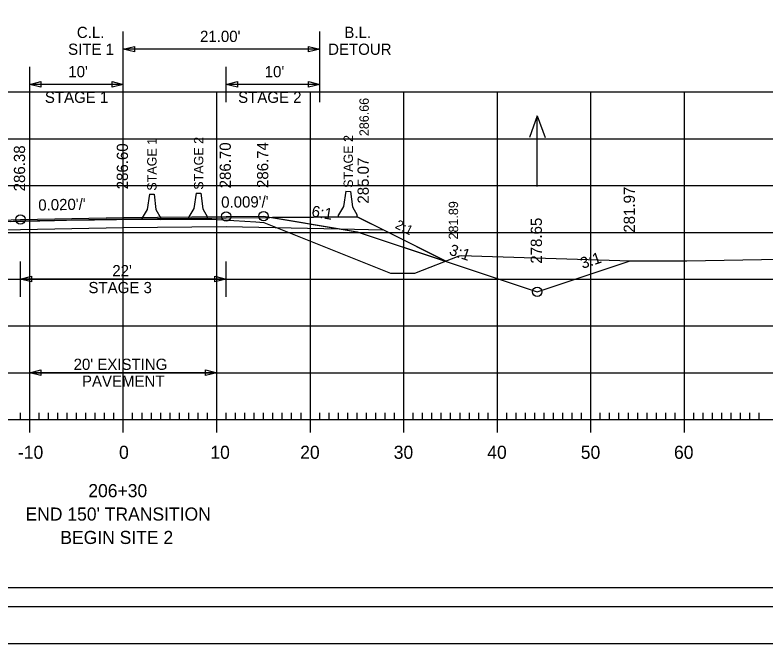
# Model space of a CAD drawing. Extents: x 1368713 to 1370673, y 380279 to 380950.
# Drawn here: x 1370498.1 to 1370578.3, y 380523.8 to 380591 of the extents above; entities that cross this region are included whole.
import ezdxf

# ---------------------------------------------------------------- set-up
doc = ezdxf.new("R2010")
doc.units = 0
for name, color, linetype in [('R_Alt Surface', 7, 'Continuous'), ('R_Axis', 7, 'Continuous'), ('R_Axis Annot', 7, 'Continuous'), ('R_Border', 7, 'Continuous'), ('R_CONC BARRIER', 7, 'Continuous'), ('R_Exist Surface', 7, 'Continuous'), ('R_Fin Surface', 7, 'Continuous'), ('R_Grid', 7, 'Continuous'), ('R_No Plot', 7, 'Continuous'), ('R_ROW Annot', 7, 'Continuous'), ('R_Stage 3 EW', 7, 'Continuous'), ('R_Water Annot', 7, 'Continuous'), ('R_Xsect Elev', 7, 'Continuous'), ('R_Xsect Slope', 7, 'Continuous')]:
    doc.layers.add(name, color=color, linetype=linetype)

msp = doc.modelspace()

# ---------------------------------------------------------------- linework, layer by layer
at = {"layer": 'R_Alt Surface'}
msp.add_line((1370532.811, 380568.128), (1370537.39, 380568.036), dxfattribs=at)
for points in [[(1370477.259, 380564.764), (1370477.379, 380564.724), (1370484.629, 380567.14), (1370487.788, 380567.667), (1370494.629, 380568.807), (1370498.629, 380568.967), (1370509.629, 380569.187), (1370520.629, 380569.288), (1370534.629, 380569.416), (1370537.737, 380567.862), (1370544.179, 380564.641)], [(1370524.629, 380569.491), (1370534.629, 380567.825)], [(1370487.788, 380567.834), (1370498.629, 380568.05), (1370509.629, 380568.27), (1370520.629, 380568.371), (1370532.811, 380568.128)], [(1370534.629, 380567.825), (1370553.886, 380561.406)], [(1370553.886, 380561.406), (1370553.886, 380561.406), (1370563.829, 380564.72)]]:
    msp.add_lwpolyline(points, dxfattribs=at)
at = {"layer": 'R_Axis'}
for p, q in [((1370499.629, 380546.354), (1370499.629, 380549.154)), ((1370509.629, 380546.354), (1370509.629, 380549.154)), ((1370519.629, 380546.354), (1370519.629, 380549.154)), ((1370529.629, 380546.354), (1370529.629, 380549.154)), ((1370539.629, 380546.354), (1370539.629, 380549.154)), ((1370549.629, 380546.354), (1370549.629, 380549.154)), ((1370559.629, 380546.354), (1370559.629, 380549.154)), ((1370569.629, 380546.354), (1370569.629, 380549.154)), ((1370498.629, 380547.754), (1370498.629, 380548.454)), ((1370500.629, 380547.754), (1370500.629, 380548.454)), ((1370501.629, 380547.754), (1370501.629, 380548.454)), ((1370502.629, 380547.754), (1370502.629, 380548.454)), ((1370503.629, 380547.754), (1370503.629, 380548.454)), ((1370504.629, 380547.754), (1370504.629, 380548.454)), ((1370505.629, 380547.754), (1370505.629, 380548.454)), ((1370506.629, 380547.754), (1370506.629, 380548.454)), ((1370507.629, 380547.754), (1370507.629, 380548.454)), ((1370508.629, 380547.754), (1370508.629, 380548.454)), ((1370510.629, 380547.754), (1370510.629, 380548.454)), ((1370511.629, 380547.754), (1370511.629, 380548.454)), ((1370512.629, 380547.754), (1370512.629, 380548.454)), ((1370513.629, 380547.754), (1370513.629, 380548.454)), ((1370514.629, 380547.754), (1370514.629, 380548.454)), ((1370515.629, 380547.754), (1370515.629, 380548.454)), ((1370516.629, 380547.754), (1370516.629, 380548.454)), ((1370517.629, 380547.754), (1370517.629, 380548.454)), ((1370518.629, 380547.754), (1370518.629, 380548.454)), ((1370520.629, 380547.754), (1370520.629, 380548.454)), ((1370521.629, 380547.754), (1370521.629, 380548.454)), ((1370522.629, 380547.754), (1370522.629, 380548.454)), ((1370523.629, 380547.754), (1370523.629, 380548.454)), ((1370524.629, 380547.754), (1370524.629, 380548.454)), ((1370525.629, 380547.754), (1370525.629, 380548.454)), ((1370526.629, 380547.754), (1370526.629, 380548.454)), ((1370527.629, 380547.754), (1370527.629, 380548.454)), ((1370528.629, 380547.754), (1370528.629, 380548.454)), ((1370530.629, 380547.754), (1370530.629, 380548.454)), ((1370531.629, 380547.754), (1370531.629, 380548.454)), ((1370532.629, 380547.754), (1370532.629, 380548.454)), ((1370533.629, 380547.754), (1370533.629, 380548.454)), ((1370534.629, 380547.754), (1370534.629, 380548.454)), ((1370535.629, 380547.754), (1370535.629, 380548.454)), ((1370536.629, 380547.754), (1370536.629, 380548.454)), ((1370537.629, 380547.754), (1370537.629, 380548.454)), ((1370538.629, 380547.754), (1370538.629, 380548.454)), ((1370540.629, 380547.754), (1370540.629, 380548.454)), ((1370541.629, 380547.754), (1370541.629, 380548.454)), ((1370542.629, 380547.754), (1370542.629, 380548.454)), ((1370543.629, 380547.754), (1370543.629, 380548.454)), ((1370544.629, 380547.754), (1370544.629, 380548.454)), ((1370545.629, 380547.754), (1370545.629, 380548.454)), ((1370546.629, 380547.754), (1370546.629, 380548.454)), ((1370547.629, 380547.754), (1370547.629, 380548.454)), ((1370548.629, 380547.754), (1370548.629, 380548.454)), ((1370550.629, 380547.754), (1370550.629, 380548.454)), ((1370551.629, 380547.754), (1370551.629, 380548.454)), ((1370552.629, 380547.754), (1370552.629, 380548.454)), ((1370553.629, 380547.754), (1370553.629, 380548.454)), ((1370554.629, 380547.754), (1370554.629, 380548.454)), ((1370555.629, 380547.754), (1370555.629, 380548.454)), ((1370556.629, 380547.754), (1370556.629, 380548.454)), ((1370557.629, 380547.754), (1370557.629, 380548.454)), ((1370558.629, 380547.754), (1370558.629, 380548.454)), ((1370560.629, 380547.754), (1370560.629, 380548.454)), ((1370561.629, 380547.754), (1370561.629, 380548.454)), ((1370562.629, 380547.754), (1370562.629, 380548.454)), ((1370563.629, 380547.754), (1370563.629, 380548.454)), ((1370564.629, 380547.754), (1370564.629, 380548.454)), ((1370565.629, 380547.754), (1370565.629, 380548.454)), ((1370566.629, 380547.754), (1370566.629, 380548.454)), ((1370567.629, 380547.754), (1370567.629, 380548.454)), ((1370568.629, 380547.754), (1370568.629, 380548.454)), ((1370570.629, 380547.754), (1370570.629, 380548.454)), ((1370571.629, 380547.754), (1370571.629, 380548.454)), ((1370572.629, 380547.754), (1370572.629, 380548.454)), ((1370573.629, 380547.754), (1370573.629, 380548.454)), ((1370574.629, 380547.754), (1370574.629, 380548.454)), ((1370575.629, 380547.754), (1370575.629, 380548.454)), ((1370576.629, 380547.754), (1370576.629, 380548.454)), ((1370577.629, 380547.754), (1370577.629, 380548.454)), ((1370369.629, 380547.754), (1370649.629, 380547.754))]:
    msp.add_line(p, q, dxfattribs=at)
at = {"layer": 'R_Border'}
msp.add_line((1370667.809, 380527.754), (1370351.629, 380527.754), dxfattribs=at)
at = {"layer": 'R_CONC BARRIER'}
for p, q in [((1370512.433, 380571.839), (1370512.933, 380571.829)), ((1370517.433, 380571.936), (1370517.933, 380571.926)), ((1370533.433, 380572.141), (1370533.933, 380572.131)), ((1370511.629, 380569.154), (1370511.632, 380569.321)), ((1370511.629, 380569.154), (1370513.629, 380569.114)), ((1370513.629, 380569.114), (1370513.632, 380569.281)), ((1370516.629, 380569.251), (1370516.633, 380569.418)), ((1370516.629, 380569.251), (1370518.629, 380569.211)), ((1370518.629, 380569.211), (1370518.632, 380569.378)), ((1370532.629, 380569.456), (1370532.633, 380569.623)), ((1370532.629, 380569.456), (1370534.629, 380569.416)), ((1370534.629, 380569.416), (1370534.632, 380569.583))]:
    msp.add_line(p, q, dxfattribs=at)
for points in [[(1370512.433, 380571.839), (1370512.181, 380570.201), (1370511.632, 380569.321)], [(1370512.933, 380571.829), (1370513.119, 380570.182), (1370513.632, 380569.281)], [(1370517.433, 380571.936), (1370517.182, 380570.298), (1370516.633, 380569.418)], [(1370517.933, 380571.926), (1370518.119, 380570.279), (1370518.632, 380569.378)], [(1370533.433, 380572.141), (1370533.182, 380570.503), (1370532.633, 380569.623)], [(1370533.933, 380572.131), (1370534.119, 380570.484), (1370534.632, 380569.583)]]:
    msp.add_lwpolyline(points, dxfattribs=at)
at = {"layer": 'R_Exist Surface'}
msp.add_lwpolyline([(1370497.525, 380568.912), (1370502.281, 380569.024), (1370503.558, 380569.041), (1370505.885, 380569.076), (1370506.558, 380569.087), (1370508.887, 380569.137), (1370509.558, 380569.149), (1370510.23, 380569.152), (1370517.615, 380569.163), (1370519.081, 380569.17), (1370523.797, 380568.881), (1370524.663, 380568.816), (1370537.646, 380563.601), (1370538.199, 380563.396), (1370540.688, 380563.397), (1370540.802, 380563.406), (1370545.547, 380565.232), (1370545.756, 380565.285), (1370547.946, 380565.225), (1370563.844, 380564.719), (1370569.867, 380564.722), (1370593.858, 380565.147)], dxfattribs=at)
at = {"layer": 'R_Fin Surface'}
for points in [[(1370476.877, 380564.724), (1370476.879, 380564.724), (1370484.629, 380567.307), (1370487.788, 380567.834), (1370494.629, 380568.974), (1370498.629, 380569.134), (1370509.629, 380569.354), (1370520.629, 380569.455), (1370524.629, 380569.491), (1370532.811, 380568.128), (1370534.629, 380567.825), (1370553.886, 380561.406), (1370563.829, 380564.72)], [(1370494.629, 380568.974), (1370498.629, 380569.134), (1370509.629, 380569.354), (1370520.629, 380569.455), (1370524.629, 380569.491)]]:
    msp.add_lwpolyline(points, dxfattribs=at)
at = {"layer": 'R_Grid'}
for p, q in [((1370369.629, 380582.754), (1370649.629, 380582.754)), ((1370499.629, 380547.754), (1370499.629, 380582.754)), ((1370509.629, 380547.754), (1370509.629, 380582.754)), ((1370519.629, 380547.754), (1370519.629, 380582.754)), ((1370529.629, 380547.754), (1370529.629, 380582.754)), ((1370539.629, 380547.754), (1370539.629, 380582.754)), ((1370549.629, 380547.754), (1370549.629, 380582.754)), ((1370559.629, 380547.754), (1370559.629, 380582.754)), ((1370569.629, 380547.754), (1370569.629, 380582.754)), ((1370369.629, 380577.754), (1370649.629, 380577.754)), ((1370369.629, 380572.754), (1370649.629, 380572.754)), ((1370369.629, 380567.754), (1370649.629, 380567.754)), ((1370369.629, 380562.754), (1370649.629, 380562.754)), ((1370369.629, 380557.754), (1370649.629, 380557.754)), ((1370369.629, 380552.754), (1370649.629, 380552.754)), ((1370369.629, 380547.754), (1370649.629, 380547.754))]:
    msp.add_line(p, q, dxfattribs=at)
at = {"layer": 'R_No Plot'}
for points in [[(1370339.221, 380737.108), (1370672.561, 380737.108), (1370672.561, 380523.771), (1370339.221, 380523.771)], [(1370353.629, 380731.214), (1370603.169, 380731.214), (1370603.169, 380721.334), (1370620.709, 380721.334), (1370644.809, 380721.334), (1370644.809, 380699.001), (1370665.809, 380699.001), (1370665.809, 380529.754), (1370353.629, 380529.754)], [(1370353.629, 380628.484), (1370665.809, 380628.484), (1370665.809, 380529.754), (1370353.629, 380529.754)]]:
    msp.add_lwpolyline(points, close=True, dxfattribs=at)
for centre in [(1370520.629, 380569.455), (1370520.629, 380569.455), (1370524.629, 380569.491), (1370524.629, 380569.491), (1370498.629, 380569.134), (1370498.629, 380569.134), (1370553.886, 380561.406), (1370553.886, 380561.406)]:
    msp.add_circle(centre, 0.5, dxfattribs=at)
at = {"layer": 'R_ROW Annot'}
for p, q in [((1370509.629, 380585.439), (1370509.629, 380589.207)), ((1370530.629, 380585.439), (1370530.629, 380589.207)), ((1370530.629, 380587.323), (1370509.629, 380587.323)), ((1370499.629, 380581.67), (1370499.629, 380585.439)), ((1370509.629, 380581.67), (1370509.629, 380585.439)), ((1370520.629, 380581.67), (1370520.629, 380585.439)), ((1370530.629, 380581.67), (1370530.629, 380585.439)), ((1370509.629, 380583.555), (1370499.629, 380583.555)), ((1370530.629, 380583.555), (1370520.629, 380583.555)), ((1370498.629, 380560.869), (1370498.629, 380564.638)), ((1370520.629, 380560.869), (1370520.629, 380564.638)), ((1370520.629, 380562.754), (1370498.629, 380562.754)), ((1370499.629, 380550.869), (1370499.629, 380554.638)), ((1370519.629, 380550.869), (1370519.629, 380554.638)), ((1370519.629, 380552.754), (1370499.629, 380552.754))]:
    msp.add_line(p, q, dxfattribs=at)
for points in [[(1370510.829, 380587.023), (1370509.629, 380587.323), (1370510.829, 380587.623)], [(1370529.429, 380587.623), (1370530.629, 380587.323), (1370529.429, 380587.023)], [(1370500.829, 380583.255), (1370499.629, 380583.555), (1370500.829, 380583.855)], [(1370508.429, 380583.855), (1370509.629, 380583.555), (1370508.429, 380583.255)], [(1370521.829, 380583.255), (1370520.629, 380583.555), (1370521.829, 380583.855)], [(1370529.429, 380583.855), (1370530.629, 380583.555), (1370529.429, 380583.255)], [(1370499.829, 380562.454), (1370498.629, 380562.754), (1370499.829, 380563.054)], [(1370519.429, 380563.054), (1370520.629, 380562.754), (1370519.429, 380562.454)], [(1370500.829, 380552.454), (1370499.629, 380552.754), (1370500.829, 380553.054)], [(1370518.429, 380553.054), (1370519.629, 380552.754), (1370518.429, 380552.454)]]:
    msp.add_lwpolyline(points, close=True, dxfattribs=at)
at = {"layer": 'R_Stage 3 EW'}
for p, q in [((1370534.629, 380569.416), (1370525.577, 380569.333)), ((1370544.107, 380564.678), (1370534.629, 380569.416)), ((1370534.629, 380567.825), (1370544.09, 380564.671)), ((1370544.09, 380564.671), (1370544.107, 380564.678))]:
    msp.add_line(p, q, dxfattribs=at)
msp.add_lwpolyline([(1370525.577, 380569.333), (1370532.811, 380568.128), (1370534.629, 380567.825)], dxfattribs=at)
at = {"layer": 'R_Water Annot'}
for p, q in [((1370553.891, 380580.203), (1370553.051, 380577.895)), ((1370553.891, 380572.662), (1370553.891, 380580.203)), ((1370553.891, 380580.203), (1370554.731, 380577.895))]:
    msp.add_line(p, q, dxfattribs=at)

# ---------------------------------------------------------------- texts
at = {"layer": 'R_Axis Annot'}
for s, p in [('-10', (1370498.367, 380543.554)), ('0', (1370509.172, 380543.554)), ('10', (1370518.94, 380543.554)), ('20', (1370528.543, 380543.554)), ('30', (1370538.543, 380543.554)), ('40', (1370548.543, 380543.554)), ('50', (1370558.543, 380543.554)), ('60', (1370568.51, 380543.554)), ('206+30', (1370505.886, 380539.454)), ("END 150' TRANSITION", (1370499.173, 380536.954)), ('BEGIN SITE 2', (1370502.894, 380534.454))]:
    msp.add_text(s, height=1.4, dxfattribs=at).set_placement(p)
at = {"layer": 'R_CONC BARRIER'}
for s, p in [(' STAGE 2', (1370518.183, 380571.931)), (' STAGE 2', (1370534.183, 380572.136)), (' STAGE 1', (1370513.183, 380571.834))]:
    msp.add_text(s, height=1, rotation=90, dxfattribs=at).set_placement(p)
at = {"layer": 'R_ROW Annot'}
for s, p in [('C.L.', (1370504.665, 380588.519)), ("21.00'", (1370517.833, 380588.093)), ('B.L.', (1370533.265, 380588.519)), ('SITE 1', (1370503.73, 380586.719)), ('DETOUR', (1370531.531, 380586.719)), ("10'", (1370503.75, 380584.324)), ("10'", (1370524.75, 380584.324)), ('STAGE 1', (1370501.246, 380581.585)), ('STAGE 2', (1370521.906, 380581.585)), ("22'", (1370508.457, 380563.054)), ('STAGE 3', (1370505.906, 380561.254)), ("20' EXISTING", (1370504.314, 380553.054)), ('PAVEMENT', (1370505.212, 380551.254))]:
    msp.add_text(s, height=1.2, dxfattribs=at).set_placement(p)
at = {"layer": 'R_Xsect Elev'}
for s, height, p in [('286.66', 1, (1370535.876, 380578.031)), ('286.60', 1.2, (1370510.129, 380572.354)), ('286.70', 1.2, (1370521.129, 380572.455)), ('286.74', 1.2, (1370525.129, 380572.491)), ('286.38', 1.2, (1370499.129, 380572.134)), ('285.07', 1.2, (1370535.876, 380570.825)), ('281.97', 1.2, (1370564.329, 380567.72)), ('281.89', 1, (1370545.426, 380566.99)), ('278.65', 1.2, (1370554.386, 380564.406))]:
    msp.add_text(s, height=height, rotation=90, dxfattribs=at).set_placement(p)
at = {"layer": 'R_Xsect Slope'}
for s, height, rotation, p in [("0.020'/'", 1.2, 1.14576, (1370500.549, 380570.072)), ("0.009'/'", 1.2, 0.52579, (1370520.097, 380570.383)), ('6:1', 1.2, 350.53766, (1370529.695, 380569.453)), ('2:1', 1, 333.43495, (1370538.616, 380568.252)), ('3:1', 1.2, 341.56507, (1370544.384, 380565.395)), ('3:1', 1.2, 18.43493, (1370558.731, 380563.842))]:
    msp.add_text(s, height=height, rotation=rotation, dxfattribs=at).set_placement(p)

doc.saveas('drawing.dxf')
